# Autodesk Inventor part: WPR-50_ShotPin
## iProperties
Author: RDG2
Shininess: 64.0
Angle Display Precision: 2
Document Length Units: 11269
Document Angle Units: 11286
Document Time Units: 11279
Document Mass Units: 11290
Document Length Units Precision: 5
Document Angle Units Precision: 2
Compacted: True
PropertySet Name: _Private Model Information
Created: 2002-02
Part Number: WPR-50_ShotPin
Material: Steel, Mild
Document SubType Name: Modeling
Designer: RDG2
Control State: 0
Master: False
Checked Out: False
PropertySet Name: Design Tracking Control
Density: 7.86
Volumn: 1279.999999999999
Area: 767.9999999999997
PropertySet Name: Model Information
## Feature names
1. Extrusion1
2. Extrusion2
3. Extrusion3
4. Extrusion4
5. Extrusion5
6. Extrusion6
7. Extrusion7
8. Hole1
9. Hole2
10. Hole3
11. Hole4
12. Extrusion8
13. Extrusion9
14. Chamfer1
15. Extrusion10
16. Chamfer2
17. Extrusion11
18. Chamfer3
19. Extrusion12
20. Extrusion13
21. Extrusion20
22. Extrusion14
23. Extrusion15
24. Extrusion16
25. Extrusion17
26. Extrusion18
27. Chamfer4
28. Extrusion19
29. Rectangular Pattern1
30. Extrusion21
31. Hole5
32. Circular Pattern1
33. Extrusion22
34. Chamfer5
35. Extrusion23
36. Extrusion24
37. Extrusion25
38. Chamfer6
39. Extrusion26
40. Hole6
41. Extrusion27
42. Fillet1
43. Circular Pattern2
